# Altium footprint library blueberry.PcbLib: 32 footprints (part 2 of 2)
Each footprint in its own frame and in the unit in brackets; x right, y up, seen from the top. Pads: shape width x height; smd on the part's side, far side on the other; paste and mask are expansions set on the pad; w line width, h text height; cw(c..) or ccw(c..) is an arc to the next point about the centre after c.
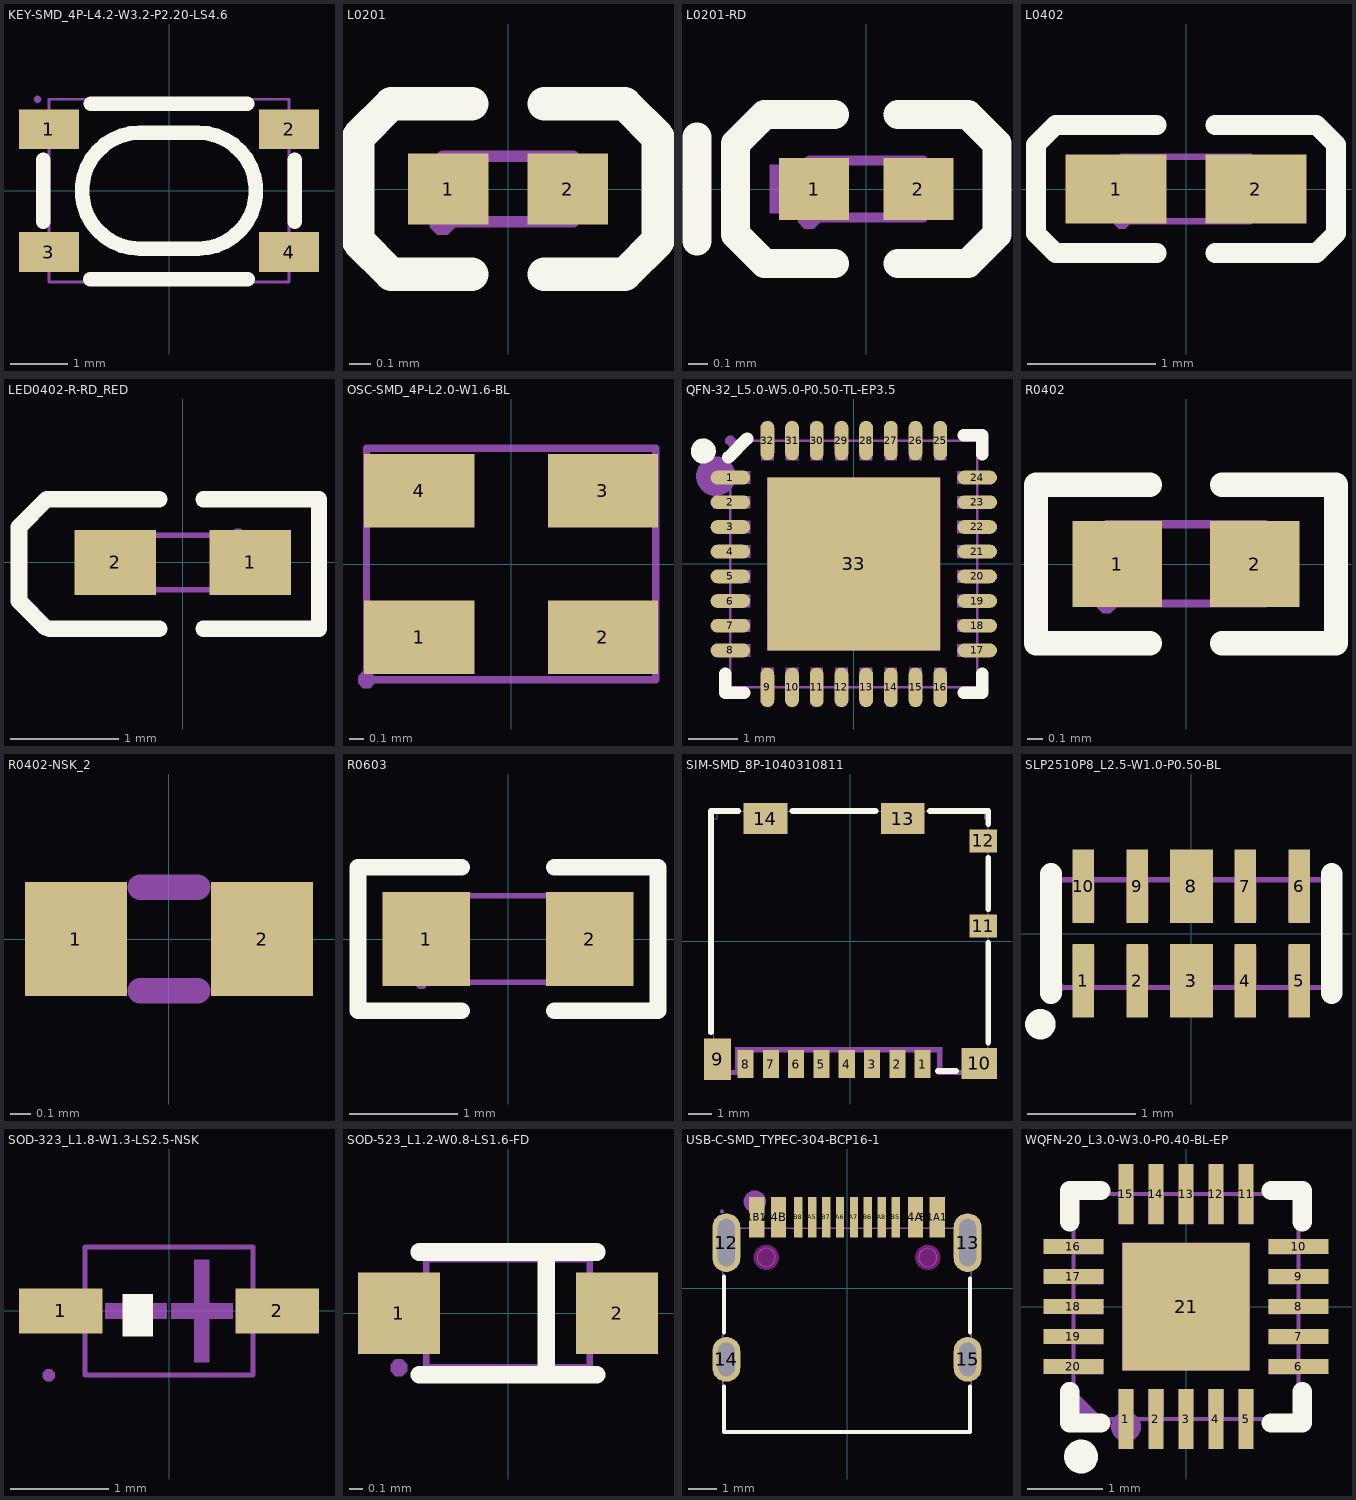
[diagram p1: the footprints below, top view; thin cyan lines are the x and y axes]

## KEY-SMD_4P-L4.2-W3.2-P2.20-LS4.6 [mm]
pads (4):
  rect 1.05x0.7 smd: 1(-2.1,1.075) 2(2.1,1.075) 3(-2.1,-1.075) 4(2.1,-1.075)
Top Overlay:
  lines w0.254: -2.2,-0.544 -2.2,0.544 ; -1.381,-1.55 1.381,-1.55 ; -1.366,1.524 1.366,1.524 ; 2.2,-0.544 2.2,0.544 ; -0.508,-1.016 cw(c-0.508,0) -0.508,1.016 0.508,1.016 cw(c0.508,0) 0.508,-1.016 -0.508,-1.016
Mechanical 15:
  region: -2.35,1.35 -1.65,1.35 -1.65,0.8 -2.35,0.8
  region: 1.651,1.35 2.351,1.35 2.351,0.8 1.651,0.8
  region: -2.35,-0.8 -1.65,-0.8 -1.65,-1.35 -2.35,-1.35
  region: 1.651,-0.8 2.351,-0.8 2.351,-1.35 1.651,-1.35
  region: -2.24,1.6 -2.241,1.624 -2.275,1.659 -2.324,1.659 -2.359,1.624 -2.36,1.6 -2.359,1.575 -2.324,1.541 -2.275,1.541 -2.241,1.575 -2.24,1.6
  lines w0.051: -2.1,-1.6 -2.1,1.6 2.1,1.6 2.1,-1.6 -2.1,-1.6
3D body "13lB-FEL-KEY-SMD_4P-L4.2-W3.2-P2.20-LS4.6.step": height 2.51, standoff 0, extent -2.349,-1.6 2.349,1.601

## L0201 [mil]
pads (2):
  rect 14.51x12.76 smd paste-3937.01 mask+2: 1(-10.8,0) 2(10.8,0)
Top Overlay:
  lines w6: -6.54,-15.38 -21.05,-15.38 -27.05,-9.38 -27.05,9.38 -21.05,15.38 -6.54,15.38 ; 6.54,-15.38 21.05,-15.38 27.05,-9.38 27.05,9.38 21.05,15.38 6.54,15.38
Top Paste:
  region: -3.19,-5.43 -3.19,5.43 -4.13,6.38 -17.1,6.38 -18.05,5.43 -18.05,-5.43 -17.1,-6.38 -4.13,-6.38
  region: 3.19,-5.43 3.19,5.43 4.13,6.38 17.1,6.38 18.05,5.43 18.05,-5.43 17.1,-6.38 4.13,-6.38
Mechanical 15:
  region: 11.81,-5.91 11.81,5.91 5.91,5.91 5.91,-5.91
  region: -11.81,-5.91 -11.81,5.91 -5.91,5.91 -5.91,-5.91
  region: -11.81,-3.55 -12.77,-3.58 -14.09,-4.95 -14.09,-6.86 -12.77,-8.24 -11.81,-8.27 -10.86,-8.24 -9.53,-6.86 -9.53,-4.95 -10.86,-3.58 -11.81,-3.55
  lines w2: -11.81,-5.91 11.81,-5.91 11.81,5.91 -11.81,5.91 -11.81,-5.91
3D body "13lB-L5-L0201.step": height 11.81, standoff 0, extent -11.81,-5.91 11.81,5.91

## L0201-RD [mil]
pads (2):
  rect 14.51x12.76 smd paste-3937.01 mask+2: 1(-10.8,0) 2(10.8,0)
Top Overlay:
  lines w6: -35,-10.8 -35,10.8 ; -6.54,-15.38 -21.05,-15.38 -27.05,-9.38 -27.05,9.38 -21.05,15.38 -6.54,15.38 ; 6.54,-15.38 21.05,-15.38 27.05,-9.38 27.05,9.38 21.05,15.38 6.54,15.38
Top Paste:
  region: -3.19,-5.43 -3.19,5.43 -4.13,6.38 -17.1,6.38 -18.05,5.43 -18.05,-5.43 -17.1,-6.38 -4.13,-6.38
  region: 3.19,-5.43 3.19,5.43 4.13,6.38 17.1,6.38 18.05,5.43 18.05,-5.43 17.1,-6.38 4.13,-6.38
Mechanical 6:
  region: -20,-5 -15,-5 -15,5 -20,5
Mechanical 15:
  region: -11.81,-3.55 -12.77,-3.58 -14.1,-4.95 -14.1,-6.86 -12.77,-8.24 -11.81,-8.27 -10.86,-8.24 -9.53,-6.87 -9.52,-4.95 -10.85,-3.58 -11.81,-3.55
  region: 11.81,-5.91 11.81,5.91 5.91,5.91 5.91,-5.91
  region: -11.81,-5.91 -11.81,5.91 -5.91,5.91 -5.91,-5.91
  lines w2: -11.81,-5.91 -11.81,5.91 11.81,5.91 11.81,-5.91 -11.81,-5.91

## L0402 [mm]
pads (2):
  rect 0.79x0.54 smd paste-100 mask+0.051: 1(-0.545,0) 2(0.545,0)
Top Overlay:
  lines w0.152: -0.226,-0.499 -1.016,-0.499 -1.169,-0.346 -1.169,0.346 -1.016,0.499 -0.226,0.499 ; 0.226,-0.499 1.016,-0.499 1.169,-0.346 1.169,0.346 1.016,0.499 0.226,0.499
Top Paste:
  region: 0.135,-0.086 0.135,0.086 0.404,0.27 0.9,0.27 0.94,0.23 0.94,-0.23 0.9,-0.27 0.404,-0.27
  region: -0.135,-0.086 -0.135,0.086 -0.404,0.27 -0.9,0.27 -0.94,0.23 -0.94,-0.23 -0.9,-0.27 -0.404,-0.27
Mechanical 15:
  region: -0.5,-0.25 -0.5,0.25 -0.25,0.25 -0.25,-0.25
  region: 0.5,-0.25 0.5,0.25 0.25,0.25 0.25,-0.25
  region: -0.5,-0.31 -0.475,-0.31 -0.44,-0.275 -0.44,-0.225 -0.475,-0.19 -0.5,-0.19 -0.525,-0.19 -0.56,-0.225 -0.56,-0.275 -0.525,-0.31 -0.5,-0.31
  lines w0.051: -0.5,-0.25 -0.5,0.25 0.5,0.25 0.5,-0.25 -0.5,-0.25
3D body "13lB-L9-L0402.step": height 0.5, standoff 0, extent -0.5,-0.25 0.5,0.25

## LED0402-R-RD_RED [mm]
pads (2):
  rect 0.75x0.6 smd: 1(0.623,0) 2(-0.623,0)
Top Overlay:
  lines w0.15: 0.191,-0.611 1.257,-0.611 1.257,0.583 0.191,0.583
  lines w0.152: -0.216,-0.611 -1.232,-0.611 -1.27,-0.598 -1.511,-0.357 -1.511,0.329 -1.257,0.583 -0.216,0.583
Mechanical 6:
  region: 0.584,-0.203 0.584,0.203 0.66,0.203 0.66,-0.203
  region: 0.406,0.038 0.813,0.038 0.813,-0.038 0.406,-0.038
  region: -0.94,0.038 -0.533,0.038 -0.533,-0.038 -0.94,-0.038
Mechanical 15:
  region: -0.297,-0.25 -0.51,-0.25 -0.51,0.25 -0.297,0.25
  region: 0.297,0.25 0.51,0.25 0.51,-0.25 0.297,-0.25
  region: 0.51,0.19 0.535,0.19 0.569,0.225 0.569,0.274 0.535,0.309 0.51,0.31 0.486,0.309 0.451,0.274 0.451,0.225 0.486,0.19 0.51,0.19
  lines w0.051: -0.5,-0.25 -0.5,0.25 0.5,0.25 0.5,-0.25 -0.5,-0.25
3D body "13lB-LED1-LED0402-R-RD_RED.step": height 0.41, standoff 0, extent -0.51,-0.25 0.51,0.26

## OSC-SMD_4P-L2.0-W1.6-BL [mil]
pads (4):
  rect 30x20 smd: 1(-25,-20) 2(25,-20) 3(25,20) 4(-25,20)
Mechanical 15:
  region: -39.37,-29.14 -40.33,-29.16 -41.68,-30.54 -41.68,-32.46 -40.33,-33.84 -39.37,-33.86 -38.41,-33.84 -37.06,-32.46 -37.06,-30.54 -38.41,-29.16 -39.37,-29.14
  lines w2: -39.37,-31.5 -39.37,31.5 39.37,31.5 39.37,-31.5 -39.37,-31.5
3D body "13lB-X2-osc-smd_4p-l2.0-w1.6-bl.step": height 31.93, standoff 0, extent -62.99,-49.21 62.99,49.22

## QFN-32_L5.0-W5.0-P0.50-TL-EP3.5 [mm]
pads (33):
  oval 0.8x0.28 smd paste-100 mask+0.051: 1(-2.5,1.75) 2(-2.5,1.25) 3(-2.5,0.75) 4(-2.5,0.25) 5(-2.5,-0.25) 6(-2.5,-0.75) 7(-2.5,-1.25) 8(-2.5,-1.75) 17(2.5,-1.75) 18(2.5,-1.25) 19(2.5,-0.75) 20(2.5,-0.25) 21(2.5,0.25) 22(2.5,0.75) 23(2.5,1.25) 24(2.5,1.75)
  oval 0.28x0.8 smd paste-100 mask+0.051: 9(-1.75,-2.5) 10(-1.25,-2.5) 11(-0.75,-2.5) 12(-0.25,-2.5) 13(0.25,-2.5) 14(0.75,-2.5) 15(1.25,-2.5) 16(1.75,-2.5) 25(1.75,2.5) 26(1.25,2.5) 27(0.75,2.5) 28(0.25,2.5) 29(-0.25,2.5) 30(-0.75,2.5) 31(-1.25,2.5) 32(-1.75,2.5)
  rect 3.5x3.5 smd paste-100 mask+0.051: 33(0,0)
Top Overlay:
  circle w0.254: c-3.048,2.286 r0.127
  lines w0.254: -2.604,-2.222 -2.604,-2.603 -2.223,-2.603 ; -2.54,2.159 -2.159,2.54 ; 2.222,-2.603 2.603,-2.603 2.603,-2.222 ; 2.222,2.604 2.603,2.604 2.603,2.223
Top Paste:
  drawing of 33 lines, arcs and shapes, not listed
Mechanical 6:
  circle w0.4: c-2.794,1.778 r0.2
Mechanical 15:
  drawing of 38 lines, arcs and shapes, not listed
3D body "13lB-U5-QFN-32_L5.0-W5.0-P0.50-TL-EP3.5.step": height 1.03, standoff 0, extent -2.5,-2.5 2.5,2.5

## R0402 [mm]
pads (2):
  rect 0.566x0.54 smd paste-100 mask+0.051: 1(-0.433,0) 2(0.433,0)
Top Overlay:
  lines w0.152: -0.226,-0.499 -0.944,-0.499 -0.944,0.499 -0.226,0.499 ; 0.226,-0.499 0.944,-0.499 0.944,0.499 0.226,0.499
Top Paste:
  region: 0.135,-0.23 0.135,0.23 0.175,0.27 0.676,0.27 0.716,0.23 0.716,-0.23 0.676,-0.27 0.175,-0.27
  region: -0.135,-0.23 -0.135,0.23 -0.175,0.27 -0.676,0.27 -0.716,0.23 -0.716,-0.23 -0.676,-0.27 -0.175,-0.27
Mechanical 15:
  region: -0.5,-0.19 -0.525,-0.19 -0.56,-0.225 -0.56,-0.275 -0.525,-0.31 -0.5,-0.31 -0.475,-0.31 -0.44,-0.275 -0.44,-0.225 -0.475,-0.19 -0.5,-0.19
  region: 0.251,-0.25 0.251,0.25 0.501,0.25 0.501,-0.25
  region: -0.249,0.25 -0.249,-0.25 -0.499,-0.25 -0.499,0.25
  lines w0.051: -0.5,-0.25 -0.5,0.25 0.5,0.25 0.5,-0.25 -0.5,-0.25
3D body "13lB-R28-R0402.step": height 0.5, standoff 0, extent -0.5,-0.25 0.5,0.25

## R0402-NSK_2 [mil]
pads (2):
  rect 19.68x22 smd paste+0 mask+2: 1(-18,0) 2(18,0)
Mechanical 6:
  lines w5: -5.5,-10 5.5,-10 ; -5.5,10 5.5,10
3D body "13lB-R8-R0402-NSK_2.step": height 14.18, standoff 0, extent -19.7,-9.85 19.7,9.89

## R0603 [mil]
pads (2):
  rect 31.75x34.02 smd paste-3937.01 mask+2: 1(-29.66,0) 2(29.66,0)
Top Overlay:
  lines w6: -16.78,-26.01 -54.53,-26.01 -54.53,26.01 -16.78,26.01 ; 16.78,-26.01 54.53,-26.01 54.53,26.01 16.78,26.01
Top Paste:
  region: -13.98,15.75 -13.98,6.77 -28.94,6.77 -28.94,-6.22 -13.98,-6.22 -13.98,-15.75 -15.94,-17.72 -47.05,-17.72 -49.02,-15.75 -49.02,15.75 -47.05,17.72 -15.94,17.72
  region: 47.05,17.72 15.55,17.72 13.58,15.75 13.58,6.77 28.15,6.77 28.15,-6.22 13.58,-6.22 13.58,-15.75 15.55,-17.72 47.05,-17.72 49.02,-15.75 49.02,15.75
Mechanical 15:
  region: 31.5,-15.75 31.5,15.75 19.68,15.75 19.68,-15.75
  region: -31.5,-15.75 -31.5,15.75 -19.68,15.75 -19.68,-15.75
  region: -31.5,-13.39 -32.46,-13.41 -33.81,-14.79 -33.81,-16.71 -32.46,-18.09 -31.5,-18.11 -30.54,-18.09 -29.19,-16.71 -29.19,-14.79 -30.54,-13.41 -31.5,-13.39
  lines w2: -31.5,-15.75 31.5,-15.75 31.5,15.75 -31.5,15.75 -31.5,-15.75
3D body "13lB-R53-R0603.step": height 17.72, standoff 0, extent -31.89,-15.94 31.89,15.94

## SIM-SMD_8P-1040310811 [mm]
pads (14):
  rect 0.7x1.2 smd paste+0 mask+0.051: 1(3.138,-5.337) 2(2.037,-5.337) 3(0.938,-5.337) 4(-0.162,-5.337) 5(-1.263,-5.337) 6(-2.363,-5.337) 7(-3.462,-5.337) 8(-4.562,-5.337)
  rect 1.17x1.8 smd paste+0 mask+0.051: 9(-5.773,-5.138)
  rect 1.55x1.35 smd paste+0 mask+0.051: 10(5.598,-5.313)
  rect 1.2x1 smd paste+0 mask+0.051: 11(5.773,0.663) 12(5.773,4.363)
  rect 1.9x1.35 smd paste+0 mask+0.051: 13(2.273,5.337) 14(-3.697,5.337)
Top Overlay:
  lines w0.254: -6.071,-3.956 -6.071,5.665 -4.879,5.665 ; -2.516,5.665 1.091,5.665 ; 3.454,5.665 5.994,5.665 5.994,5.094 ; 3.794,-5.638 4.591,-5.638 ; 5.994,-4.406 5.994,-0.069 ; 5.994,1.394 5.994,3.631
Mechanical 6:
  region: -5,-4.8 4,-4.8 4,-4.6 -5,-4.6
  region: -4.8,-5.6 -4.8,-4.8 -5,-4.8 -5,-5.6
  region: 3.8,-5.6 3.8,-4.8 4,-4.8 4,-5.6
  region: 3.8,-5.8 6,-5.8 6,-5.6 3.8,-5.6
  region: -6,-5.8 -4.8,-5.8 -4.8,-5.6 -6,-5.6
Mechanical 15:
  region: 2.968,-4.75 3.308,-4.75 3.308,-5.7 2.968,-5.7
  region: 1.867,-4.75 2.207,-4.75 2.207,-5.7 1.867,-5.7
  region: 0.768,-4.75 1.108,-4.75 1.108,-5.7 0.768,-5.7
  region: -0.332,-4.75 0.008,-4.75 0.008,-5.7 -0.332,-5.7
  region: -1.432,-4.75 -1.092,-4.75 -1.092,-5.7 -1.432,-5.7
  region: -2.533,-4.75 -2.193,-4.75 -2.193,-5.7 -2.533,-5.7
  region: -3.632,-4.75 -3.292,-4.75 -3.292,-5.7 -3.632,-5.7
  region: -4.732,-4.75 -4.392,-4.75 -4.392,-5.7 -4.732,-5.7
  region: -4.397,5.65 -2.997,5.65 -2.997,4.75 -4.397,4.75
  region: 1.572,5.65 2.972,5.65 2.972,4.75 1.572,4.75
  region: 5.352,4.688 6.002,4.688 6.002,4.038 5.352,4.038
  region: 5.352,0.988 6.002,0.988 6.002,0.338 5.352,0.338
  region: 5.002,-4.9 6.002,-4.9 6.002,-5.75 5.002,-5.75
  region: -5.963,-4.437 -5.313,-4.437 -5.313,-5.738 -5.963,-5.738
  region: 6.002,-5.69 5.978,-5.691 5.944,-5.726 5.944,-5.774 5.978,-5.809 6.002,-5.81 6.026,-5.809 6.06,-5.774 6.06,-5.726 6.026,-5.691 6.002,-5.69
  lines w0.051: -5.95,-5.75 -5.95,5.33 -5.8,5.33 -5.8,5.65 5.85,5.65 5.85,5.33 6,5.33 6,-5.75 3.8,-5.75 3.8,-4.8 -4.86,-4.8 -4.86,-5.75 -5.95,-5.75
3D body "13lB-SIM1-SIM-SMD_8P-1040310811.step": height 1.47, standoff 0, extent -5.975,-5.75 5.975,5.65

## SLP2510P8_L2.5-W1.0-P0.50-BL [mil]
pads (10):
  rect 7.9x26.8 smd paste+0 mask+2: 1(-39.4,-17.3) 2(-19.7,-17.3) 4(19.7,-17.3) 5(39.4,-17.3) 6(39.4,17.3) 7(19.7,17.3) 9(-19.7,17.3) 10(-39.4,17.3)
  rect 15.7x26.8 smd paste+0 mask+2: 3(0,-17.3) 8(0,17.3)
Top Overlay:
  circle w7.9: c-55.1,-33.1 r1.6
  lines w7.9: -51.2,-21.7 -51.2,21.7 ; 51.2,-21.7 51.2,21.7
Mechanical 6:
  circle w3.9: c-39.4,-17.3 r2
Mechanical 15:
  region: -51.6,-19.7 -51.6,-20.69 -50.19,-22.1 -48.21,-22.1 -46.8,-20.69 -46.8,-19.7 -46.8,-18.71 -48.21,-17.3 -50.19,-17.3 -51.6,-18.71 -51.6,-19.7
  region: 15.8,-4.7 23.6,-4.7 23.6,-19.7 15.8,-19.7
  region: 35.4,-4.7 43.3,-4.7 43.3,-19.7 35.4,-19.7
  region: -15.8,4.7 -23.6,4.7 -23.6,19.7 -15.8,19.7
  region: -35.4,4.7 -43.3,4.7 -43.3,19.7 -35.4,19.7
  region: 43.3,4.7 35.4,4.7 35.4,19.7 43.3,19.7
  region: 23.6,4.7 15.8,4.7 15.8,19.7 23.6,19.7
  region: -7.5,-4.7 7.5,-4.7 7.5,-20.5 -7.5,-20.5
  region: -23.6,-4.7 -15.8,-4.7 -15.8,-19.7 -23.6,-19.7
  region: -43.3,-4.7 -35.4,-4.7 -35.4,-19.7 -43.3,-19.7
  region: 7.5,4.7 -7.5,4.7 -7.5,20.5 7.5,20.5
  lines w2: -49.2,-19.7 49.2,-19.7 49.2,19.7 -49.2,19.7 -49.2,-19.7
3D body "13lB-D21-SLP2510P8_L2.5-W1.0-P0.50-BL.step": height 22.44, standoff 0, extent -48.28,-19.7 48.28,19.7

## SOD-323_L1.8-W1.3-LS2.5-NSK [mil]
pads (2):
  rect 33.3x17.9 smd paste+0 mask+2: 1(-43.2,0) 2(43.2,0)
Top Overlay:
  region: -6.5,6.6 -6.5,-10 -18.5,-10 -18.5,6.6
Mechanical 6:
  region: -25.4,3.1 -25.4,-3.1 -0.8,-3.1 -0.8,3.1
  region: 25.4,3.1 25.4,-3.1 0.8,-3.1 0.8,3.1
  region: 16.1,20.5 16.1,-20.5 10,-20.5 10,20.5
Mechanical 15:
  region: -50.4,-25.6 -50.4,-26.59 -48.99,-28 -47.01,-28 -45.6,-26.59 -45.6,-25.6 -45.6,-24.61 -47.01,-23.2 -48.99,-23.2 -50.4,-24.61 -50.4,-25.6
  region: -33.1,6.3 -33.1,-6.3 -37.8,-6.3 -37.8,6.3
  region: -37.4,6.3 -37.4,-6.3 -49.2,-6.3 -49.2,6.3
  region: 37.8,6.3 37.8,-6.3 33.1,-6.3 33.1,6.3
  region: 49.2,6.3 49.2,-6.3 37.4,-6.3 37.4,6.3
  lines w2: -33.5,-25.6 33.5,-25.6 33.5,25.6 -33.5,25.6 -33.5,-25.6
3D body "13lB-D23-SOD-323_L1.8-W1.3-LS2.5-NSK.step": height 47.21, standoff 0, extent -48.47,-25.59 50.44,25.59

## SOD-523_L1.2-W0.8-LS1.6-FD [mil]
pads (2):
  rect 23.6x23.6 smd paste+0 mask+2: 1(-31.5,0) 2(31.5,0)
Top Overlay:
  lines w5.1: -25.6,-17.7 25.6,-17.7 ; -25.6,17.7 25.6,17.7 ; 11,-17.5 11,16
Mechanical 6:
  region: -39.4,2 -25.6,2 -25.6,-2 -39.4,-2
  region: 23.6,2 37.4,2 37.4,-2 23.6,-2
  region: -34.5,10.5 -30.6,10.5 -30.6,-11.2 -34.5,-11.2
Mechanical 15:
  region: -33.9,-15.7 -33.9,-16.69 -32.49,-18.1 -30.51,-18.1 -29.1,-16.69 -29.1,-15.7 -29.1,-14.71 -30.51,-13.3 -32.49,-13.3 -33.9,-14.71 -33.9,-15.7
  region: -31.5,5.9 -20,5.9 -20,-5.9 -31.5,-5.9
  region: 31.5,-5.9 20,-5.9 20,5.9 31.5,5.9
  lines w2: -23.6,-15.7 23.6,-15.7 23.6,15.7 -23.6,15.7 -23.6,-15.7
3D body "13lB-D20-SOD-523_L1.2-W0.8-LS1.6-FD.step": height 27.96, standoff 0, extent -31.5,-15.75 31.5,15.75

## USB-C-SMD_TYPEC-304-BCP16-1 [mil]
pads (16):
  oval 39.4x82.7 hole 23.6 slot 66.9 at 90 deg paste-99999 mask+1.97: 12(-170.1,64.3) 13(170.1,64.3)
  oval 39.4x63 hole 23.6 slot 47.2 at 90 deg paste-99999 mask+1.97: 14(-170.1,-100.3) 15(170.1,-100.3)
  rect 21.7x57.1 smd paste-3937.01 mask+1.97: A1B12(-127,100.3) A4B9(-96.5,100.3) B1A12(127,100.3) B4A9(96.5,100.3)
  rect 11.8x57.1 smd paste-3937.01 mask+1.97: A5(-49.2,100.3) A6(-9.8,100.3) A7(9.8,100.3) A8(49.2,100.3) B5(68.9,100.3) B6(29.5,100.3) B7(-29.5,100.3) B8(-68.9,100.3)
Top Overlay:
  lines w5.9: -173.2,-138.7 -173.2,-202.6 173.2,-202.6 173.2,-138.7 ; -173.2,-61.9 -173.2,16.1 ; 173.2,-61.9 173.2,13.9
Top Paste:
  region: 150.4,-88.5 150.4,-84.58 153.4,-77.34 158.94,-71.8 166.18,-68.8 174.02,-68.8 181.26,-71.8 186.8,-77.34 189.8,-84.58 189.8,-88.5 189.8,-112.1 189.8,-116.02 186.8,-123.26 181.26,-128.8 174.02,-131.8 166.18,-131.8 158.94,-128.8 153.4,-123.26 150.4,-116.02 150.4,-112.1
  region: -189.8,-88.5 -189.8,-84.58 -186.8,-77.34 -181.26,-71.8 -174.02,-68.8 -166.18,-68.8 -158.94,-71.8 -153.4,-77.34 -150.4,-84.58 -150.4,-88.5 -150.4,-112.1 -150.4,-116.02 -153.4,-123.26 -158.94,-128.8 -166.18,-131.8 -174.02,-131.8 -181.26,-128.8 -186.8,-123.26 -189.8,-116.02 -189.8,-112.1
  region: 150.4,85.9 150.4,89.82 153.4,97.06 158.94,102.6 166.18,105.6 174.02,105.6 181.26,102.6 186.8,97.06 189.8,89.82 189.8,85.9 189.8,42.6 189.8,38.68 186.8,31.44 181.26,25.9 174.02,22.9 166.18,22.9 158.94,25.9 153.4,31.44 150.4,38.68 150.4,42.6
  region: -189.8,85.9 -189.8,89.82 -186.8,97.06 -181.26,102.6 -174.02,105.6 -166.18,105.6 -158.94,102.6 -153.4,97.06 -150.4,89.82 -150.4,85.9 -150.4,42.6 -150.4,38.68 -153.4,31.44 -158.94,25.9 -166.18,22.9 -174.02,22.9 -181.26,25.9 -186.8,31.44 -189.8,38.68 -189.8,42.6
  region: 84.6,128.8 108.3,128.8 108.3,71.7 84.6,71.7
  region: 63,128.8 74.8,128.8 74.8,71.7 63,71.7
  region: 43.3,128.8 55.1,128.8 55.1,71.7 43.3,71.7
  region: 23.6,128.8 35.4,128.8 35.4,71.7 23.6,71.7
  region: 3.9,128.8 15.7,128.8 15.7,71.7 3.9,71.7
  region: -15.7,128.8 -3.9,128.8 -3.9,71.7 -15.7,71.7
  region: -35.4,128.8 -23.6,128.8 -23.6,71.7 -35.4,71.7
  region: -55.1,128.8 -43.3,128.8 -43.3,71.7 -55.1,71.7
  region: -74.8,128.8 -63,128.8 -63,71.7 -74.8,71.7
  region: -108.3,128.8 -84.6,128.8 -84.6,71.7 -108.3,71.7
  region: 115.2,128.8 138.8,128.8 138.8,71.7 115.2,71.7
  region: -138.8,128.8 -115.2,128.8 -115.2,71.7 -138.8,71.7
Keep-Out Layer:
  board cut-out: 126.6,43.4 126.6,45.95 124.65,50.65 121.05,54.25 116.35,56.2 111.25,56.2 106.55,54.25 102.95,50.65 101,45.95 101,43.4 101,40.85 102.95,36.15 106.55,32.55 111.25,30.6 116.35,30.6 121.05,32.55 124.65,36.15 126.6,40.85
  board cut-out: -101,43.4 -101,45.95 -102.95,50.65 -106.55,54.25 -111.25,56.2 -116.35,56.2 -121.05,54.25 -124.65,50.65 -126.6,45.95 -126.6,43.4 -126.6,40.85 -124.65,36.15 -121.05,32.55 -116.35,30.6 -111.25,30.6 -106.55,32.55 -102.95,36.15 -101,40.85
Keep-Out Layer:
  circle w10: c113.8,43.4 r12.8
  circle w0.2: c113.8,43.4 r12.8
  circle w10: c-113.8,43.4 r12.8
  circle w0.2: c-113.8,43.4 r12.8
Mechanical 1:
  circle w0.2: c113.8,43.4 r12.8
  circle w0.2: c-113.8,43.4 r12.8
Mechanical 6:
  circle w15.7: c-129.9,122.1 r7.9
Mechanical 15:
  region: 164.2,-84.5 176,-84.5 176,-116 164.2,-116
  region: -176,-84.5 -164.2,-84.5 -164.2,-116 -176,-116
  region: 164.2,84.9 176,84.9 176,43.6 164.2,43.6
  region: -176,84.9 -164.2,84.9 -164.2,43.6 -176,43.6
  region: 119.1,108.4 134.8,108.4 134.8,73 119.1,73
  region: 88.6,108.4 104.3,108.4 104.3,73 88.6,73
  region: -104.3,108.4 -88.6,108.4 -88.6,73 -104.3,73
  region: -134.8,108.4 -119.1,108.4 -119.1,73 -134.8,73
  region: 65,108.4 72.8,108.4 72.8,73 65,73
  region: 45.3,108.4 53.1,108.4 53.1,73 45.3,73
  region: 25.6,108.4 33.5,108.4 33.5,73 25.6,73
  region: 5.9,108.4 13.8,108.4 13.8,73 5.9,73
  region: -13.8,108.4 -5.9,108.4 -5.9,73 -13.8,73
  region: -33.5,108.4 -25.6,108.4 -25.6,73 -33.5,73
  region: -53.1,108.4 -45.3,108.4 -45.3,73 -53.1,73
  region: -72.8,108.4 -65,108.4 -65,73 -72.8,73
  region: -173.6,108.4 -173.6,109.39 -175.01,110.8 -176.99,110.8 -178.4,109.39 -178.4,108.4 -178.4,107.41 -176.99,106 -175.01,106 -173.6,107.41 -173.6,108.4
  lines w2: -175.2,-202.6 175.2,-202.6 175.2,84.8 -175.2,84.8 -175.2,-202.6
3D body "13lB-USB3-USB-C-SMD_TYPEC-304-BCP16-1.step": height 127.39, standoff -38, extent -175.98,-199.56 175.98,105.56

## WQFN-20_L3.0-W3.0-P0.40-BL-EP [mil]
pads (21):
  rect 7.9x31.5 smd paste+0 mask+2: 1(-31.5,-59.1) 2(-15.8,-59.1) 3(0,-59.1) 4(15.7,-59.1) 5(31.5,-59.1) 11(31.5,59.1) 12(15.7,59.1) 13(0,59.1) 14(-15.8,59.1) 15(-31.5,59.1)
  rect 31.5x7.9 smd paste+0 mask+2: 6(59.1,-31.5) 7(59.1,-15.7) 8(59.1,0) 9(59.1,15.7) 10(59.1,31.5) 16(-59.1,31.5) 17(-59.1,15.8) 18(-59.1,0) 19(-59.1,-15.7) 20(-59.1,-31.5)
  rect 66.9x66.9 smd paste+0 mask+2: 21(0,0)
Top Overlay:
  circle w10: c-55.1,-78.7 r3.9
  lines w10: -61,-44.5 -61,-61 -44.5,-61 ; -61,44.5 -61,61 -44.5,61 ; 44.5,-61 61,-61 61,-44.5 ; 44.5,61 61,61 61,44.5
Mechanical 6:
  circle w7.9: c-31.5,-63 r3.9
  region: -63,-63 -63,-39.4 -39.4,-63
Mechanical 15:
  region: -61.5,-59 -61.49,-59.99 -60.08,-61.37 -58.11,-61.37 -56.71,-59.98 -56.7,-59 -56.71,-58.01 -58.12,-56.62 -60.09,-56.63 -61.49,-58.01 -61.5,-59
  region: -59.1,-35.4 -59.1,-27.6 -43.3,-27.6 -43.3,-35.4
  region: -59.1,-19.7 -59.1,-11.8 -43.3,-11.8 -43.3,-19.7
  region: -59.1,-3.9 -59.1,3.9 -43.3,3.9 -43.3,-3.9
  region: -59.1,11.8 -59.1,19.7 -43.3,19.7 -43.3,11.8
  region: -59.1,27.6 -59.1,35.4 -43.3,35.4 -43.3,27.6
  region: -27.6,43.3 -35.4,43.3 -35.4,59.1 -27.6,59.1
  region: -11.8,43.3 -19.7,43.3 -19.7,59.1 -11.8,59.1
  region: 3.9,43.3 -3.9,43.3 -3.9,59.1 3.9,59.1
  region: 19.7,43.3 11.8,43.3 11.8,59.1 19.7,59.1
  region: 35.4,43.3 27.6,43.3 27.6,59.1 35.4,59.1
  region: 59.1,35.4 59.1,27.6 43.3,27.6 43.3,35.4
  region: 59.1,19.7 59.1,11.8 43.3,11.8 43.3,19.7
  region: 59.1,3.9 59.1,-3.9 43.3,-3.9 43.3,3.9
  region: 59.1,-11.8 59.1,-19.7 43.3,-19.7 43.3,-11.8
  region: 59.1,-27.6 59.1,-35.4 43.3,-35.4 43.3,-27.6
  region: 35.4,-59 27.6,-59 27.6,-43.3 35.4,-43.3
  region: 19.7,-59 11.8,-59 11.8,-43.3 19.7,-43.3
  region: 3.9,-59 -3.9,-59 -3.9,-43.3 3.9,-43.3
  region: -11.8,-59 -19.7,-59 -19.7,-43.3 -11.8,-43.3
  region: -27.6,-59 -35.4,-59 -35.4,-43.3 -27.6,-43.3
  region: -33.5,-33.5 -33.5,33.5 33.5,33.5 33.5,-33.5
  lines w2: -59.1,-59 -59.1,59.1 59.1,59.1 59.1,-59 -59.1,-59
3D body "13lB-U1-WQFN-20_L3.0-W3.0-P0.40-BL-EP.step": height 32.67, standoff 0, extent -59.44,-59.44 59.44,59.44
